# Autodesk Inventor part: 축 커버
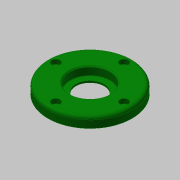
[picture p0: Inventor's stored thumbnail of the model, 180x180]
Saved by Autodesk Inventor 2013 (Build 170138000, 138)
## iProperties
Created: 2015-10
Part Number: 축 커버
Document SubType Name: Modeling
Designer: mdu
Density: 1 g/cm^3
Material: 일반
Author: mdu
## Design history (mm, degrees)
sketch "스케치1"
  geometry: C1 r 40 at (0, 0) reference; C2 r 26 at (0, 0) reference; 1 further point
  node "참조1"
  node "참조2"
extrude "돌출1" new body sketch "스케치1" distance "d0" = 10; taper "d1" = 0 deg
extrude "돌출2" join sketch "스케치1" distance "d2" = 3; taper "d3" = 0 deg
hole "구멍1" diameter "d6" = 27; stored, may be unused: countersink angle "d10" = 90 deg, drill point angle "d12" = 118 deg; dims "d7" = 6, "d8" = 38, "d9" = 8.3, "d11" = 8, "d31" = 10, "d32" = 10
sketch "스케치2"
  geometry: C1 r 20 at (0, 0); 1 further point
  constraints: 1 centre point, 1 coincident
  dimensions: "d13" = 40 diameter of C1
extrude "돌출3" cut sketch "스케치2" distance "d14" = 3; taper "d15" = 0 deg
sketch "스케치3"
  geometry: C1 r 1.621 at (0, 32.5) reference; 1 further point
hole "구멍2" sketch "스케치3" at (0, 32.5) diameter "d16" = 4.5; stored, may be unused: countersink angle "d20" = 90 deg, drill point angle "d22" = 118 deg; dims "d17" = 6, "d18" = 8, "d19" = 4.4, "d21" = 8
fillet "모깎기1" dims "d26" = 3, "d27" = 0.3
chamfer "모따기1" distance "d28" = 1; stored, may be unused: second distance "d29" = 2, angle "d30" = 45 deg
node "솔리드1"
pattern_circular "원형 패턴1" dims angle "d24" = 360 deg
node "참조3"
